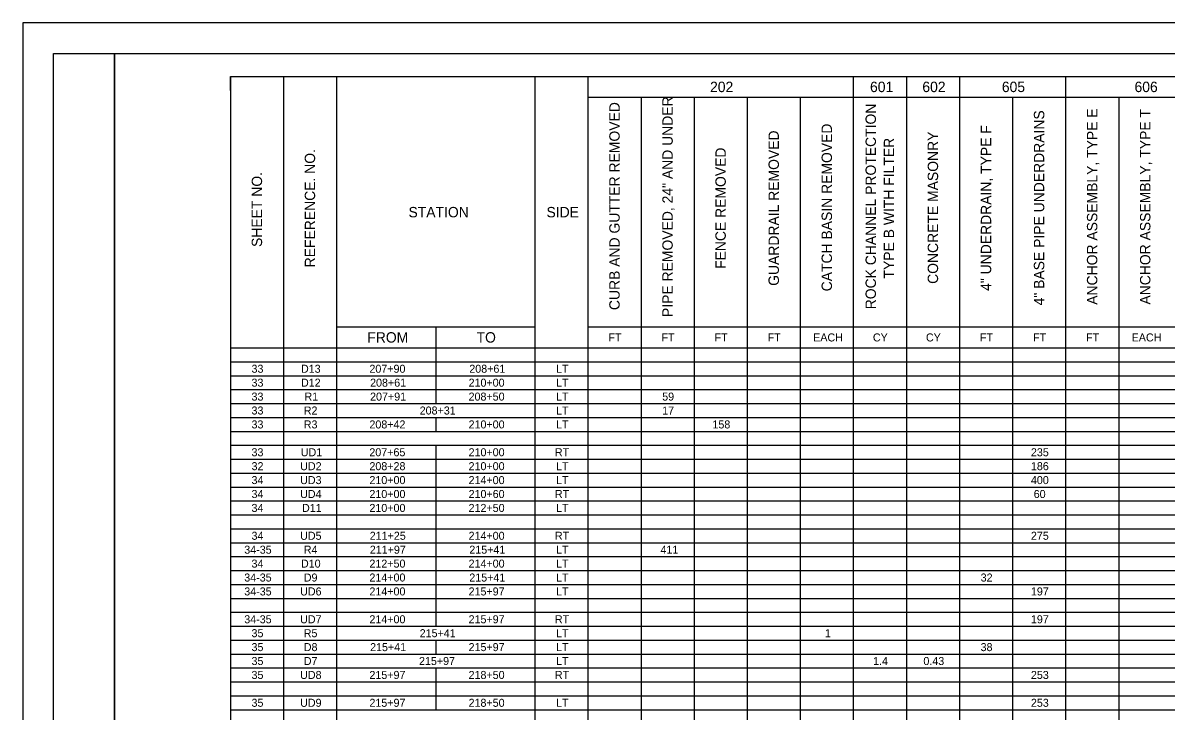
# Model space of a CAD drawing. Extents: x 0 to 37.4, y 0 to 22.
# Drawn here: x 0 to 18.72, y 10.72 to 22 of the extents above; entities that cross this region are included whole.
import ezdxf

# ---------------------------------------------------------------- set-up
doc = ezdxf.new("R2010")
doc.units = 0
for name, color, linetype in [('SH_Border', 7, 'Continuous'), ('SH_Cut_Line', 7, 'Continuous'), ('SH_Text', 7, 'Continuous')]:
    doc.layers.add(name, color=color, linetype=linetype)

msp = doc.modelspace()

# ---------------------------------------------------------------- linework, layer by layer
at = {"layer": 'SH_Border'}
for points in [[(0.5, 21.5), (1.5, 21.5), (1.5, 0.5), (0.5, 0.5)], [(1.5, 21.5), (33.5, 21.5), (33.5, 0.5), (1.5, 0.5)]]:
    msp.add_lwpolyline(points, close=True, dxfattribs=at)
at = {"layer": 'SH_Cut_Line'}
msp.add_lwpolyline([(0, 0), (34, 0), (34, 22), (0, 22)], close=True, dxfattribs=at)
at = {"layer": 'SH_Text'}
for p, q in [((3.398, 21.122), (30.117, 21.122)), ((3.398, 21.122), (3.398, 1.044)), ((4.268, 21.122), (4.268, 1.4)), ((5.137, 21.122), (5.137, 1.4)), ((8.386, 21.122), (8.386, 1.4)), ((9.255, 21.122), (9.255, 1.044)), ((13.601, 21.122), (13.601, 1.044)), ((14.471, 21.122), (14.471, 1.044)), ((15.34, 21.122), (15.34, 1.044)), ((17.078, 21.122), (17.078, 1.044)), ((9.255, 20.78), (30.117, 20.78)), ((10.124, 20.78), (10.124, 1.044)), ((10.994, 20.78), (10.994, 1.044)), ((11.863, 20.78), (11.863, 1.044)), ((12.732, 20.78), (12.732, 1.044)), ((16.209, 20.78), (16.209, 1.044)), ((17.948, 20.78), (17.948, 1.044)), ((5.137, 17.018), (8.386, 17.018)), ((6.761, 17.018), (6.761, 15.764)), ((9.255, 17.018), (30.117, 17.018)), ((3.398, 16.676), (30.117, 16.676)), ((3.398, 16.448), (30.117, 16.448)), ((3.398, 16.22), (30.117, 16.22)), ((3.398, 15.992), (30.117, 15.992)), ((3.398, 15.764), (30.117, 15.764)), ((3.398, 15.536), (30.117, 15.536)), ((6.761, 15.536), (6.761, 15.308)), ((3.398, 15.308), (30.117, 15.308)), ((3.398, 15.08), (30.117, 15.08)), ((6.761, 15.08), (6.761, 12.116)), ((3.398, 14.852), (30.117, 14.852)), ((3.398, 14.624), (30.117, 14.624)), ((3.398, 14.396), (30.117, 14.396)), ((3.398, 14.168), (30.117, 14.168)), ((3.398, 13.94), (30.117, 13.94)), ((3.398, 13.712), (30.117, 13.712)), ((3.398, 13.484), (30.117, 13.484)), ((3.398, 13.256), (30.117, 13.256)), ((3.398, 13.028), (30.117, 13.028)), ((3.398, 12.8), (30.117, 12.8)), ((3.398, 12.572), (30.117, 12.572)), ((3.398, 12.344), (30.117, 12.344)), ((3.398, 12.116), (30.117, 12.116)), ((3.398, 11.888), (30.117, 11.888)), ((6.761, 11.888), (6.761, 11.66)), ((3.398, 11.66), (30.117, 11.66)), ((3.398, 11.432), (30.117, 11.432)), ((6.761, 11.432), (6.761, 10.748)), ((3.398, 11.204), (30.117, 11.204)), ((3.398, 10.976), (30.117, 10.976)), ((3.398, 10.748), (30.117, 10.748))]:
    msp.add_line(p, q, dxfattribs=at)
for points in [[(3.398, 21.122), (3.398, 21.122), (3.398, 21.122), (3.398, 21.122)], [(3.398, 21.122), (3.398, 21.122), (3.398, 20.894), (3.398, 20.894)], [(3.398, 21.122), (3.398, 21.122), (3.398, 20.894), (3.398, 20.894)], [(3.398, 21.122), (3.398, 21.122), (3.398, 20.894), (3.398, 20.894)], [(3.398, 21.122), (3.398, 21.122), (3.398, 20.894), (3.398, 20.894)], [(3.398, 21.122), (3.398, 21.122), (3.398, 20.894), (3.398, 20.894)], [(3.398, 21.122), (3.398, 21.122), (3.398, 20.894), (3.398, 20.894)], [(3.398, 21.122), (3.398, 21.122), (3.398, 20.894), (3.398, 20.894)], [(3.398, 21.122), (3.398, 21.122), (3.398, 20.894), (3.398, 20.894)], [(3.398, 21.122), (3.398, 21.122), (3.398, 20.894), (3.398, 20.894)], [(3.398, 21.122), (3.398, 21.122), (3.398, 20.894), (3.398, 20.894)], [(3.398, 21.122), (3.398, 21.122), (3.398, 20.894), (3.398, 20.894)], [(3.398, 21.122), (3.398, 21.122), (3.398, 20.894), (3.398, 20.894)], [(3.398, 21.122), (3.398, 21.122), (3.398, 20.894), (3.398, 20.894)], [(3.398, 21.122), (3.398, 21.122), (3.398, 20.894), (3.398, 20.894)], [(3.398, 21.122), (3.398, 21.122), (3.398, 20.894), (3.398, 20.894)], [(3.398, 21.122), (3.398, 21.122), (3.398, 20.894), (3.398, 20.894)], [(3.398, 21.122), (3.398, 21.122), (3.398, 20.894), (3.398, 20.894)], [(3.398, 21.122), (3.398, 21.122), (3.398, 20.894), (3.398, 20.894)], [(3.398, 21.122), (3.398, 21.122), (3.398, 20.894), (3.398, 20.894)], [(3.398, 21.122), (3.398, 21.122), (3.398, 20.894), (3.398, 20.894)], [(3.398, 21.122), (3.398, 21.122), (3.398, 20.894), (3.398, 20.894)], [(3.398, 21.122), (3.398, 21.122), (3.398, 20.894), (3.398, 20.894)], [(3.398, 21.122), (3.398, 21.122), (3.398, 20.894), (3.398, 20.894)], [(3.398, 21.122), (3.398, 21.122), (3.398, 20.894), (3.398, 20.894)], [(3.398, 21.122), (3.398, 21.122), (3.398, 20.894), (3.398, 20.894)], [(3.398, 21.122), (3.398, 21.122), (3.398, 20.894), (3.398, 20.894)], [(3.398, 21.122), (3.398, 21.122), (3.398, 20.894), (3.398, 20.894)], [(3.398, 21.122), (3.398, 21.122), (3.398, 20.894), (3.398, 20.894)], [(3.398, 21.122), (3.398, 21.122), (3.398, 20.894), (3.398, 20.894)], [(3.398, 21.122), (3.398, 21.122), (3.398, 20.894), (3.398, 20.894)], [(3.398, 21.122), (3.398, 21.122), (3.398, 20.894), (3.398, 20.894)], [(3.398, 21.122), (3.398, 21.122), (3.398, 20.894), (3.398, 20.894)], [(3.398, 21.122), (3.398, 21.122), (3.398, 20.894), (3.398, 20.894)], [(3.398, 21.122), (3.398, 21.122), (3.398, 20.894), (3.398, 20.894)], [(3.398, 21.122), (3.398, 21.122), (3.398, 20.894), (3.398, 20.894)], [(3.398, 21.122), (3.398, 21.122), (3.398, 20.894), (3.398, 20.894)], [(3.398, 21.122), (3.398, 21.122), (3.398, 20.894), (3.398, 20.894)], [(3.398, 21.122), (3.398, 21.122), (3.398, 20.894), (3.398, 20.894)], [(3.398, 21.122), (3.398, 21.122), (3.398, 20.894), (3.398, 20.894)], [(3.398, 21.122), (3.398, 21.122), (3.398, 20.894), (3.398, 20.894)], [(3.398, 21.122), (3.398, 21.122), (3.398, 20.894), (3.398, 20.894)], [(3.398, 21.122), (3.398, 21.122), (3.398, 20.894), (3.398, 20.894)], [(3.398, 21.122), (3.398, 21.122), (3.398, 20.894), (3.398, 20.894)], [(3.398, 21.122), (3.398, 21.122), (3.398, 20.894), (3.398, 20.894)], [(3.398, 21.122), (3.398, 21.122), (3.398, 20.894), (3.398, 20.894)], [(3.398, 21.122), (3.398, 21.122), (3.398, 20.894), (3.398, 20.894)], [(3.398, 21.122), (3.398, 21.122), (3.398, 20.894), (3.398, 20.894)], [(3.398, 21.122), (3.398, 21.122), (3.398, 20.894), (3.398, 20.894)], [(3.398, 21.122), (3.398, 21.122), (3.398, 20.894), (3.398, 20.894)], [(3.398, 21.122), (3.398, 21.122), (3.398, 20.894), (3.398, 20.894)], [(3.398, 21.122), (3.398, 21.122), (3.398, 20.894), (3.398, 20.894)], [(3.398, 21.122), (3.398, 21.122), (3.398, 20.894), (3.398, 20.894)], [(3.398, 21.122), (3.398, 21.122), (3.398, 20.894), (3.398, 20.894)], [(3.398, 21.122), (3.398, 21.122), (3.398, 20.894), (3.398, 20.894)], [(3.398, 21.122), (3.398, 21.122), (3.398, 20.894), (3.398, 20.894)], [(3.398, 21.122), (3.398, 21.122), (3.398, 20.894), (3.398, 20.894)], [(3.398, 21.122), (3.398, 21.122), (3.398, 20.894), (3.398, 20.894)], [(3.398, 21.122), (3.398, 21.122), (3.398, 20.894), (3.398, 20.894)], [(3.398, 21.122), (3.398, 21.122), (3.398, 20.894), (3.398, 20.894)], [(3.398, 21.122), (3.398, 21.122), (3.398, 20.894), (3.398, 20.894)], [(3.398, 21.122), (3.398, 21.122), (3.398, 20.894), (3.398, 20.894)], [(3.398, 21.122), (3.398, 21.122), (3.398, 20.894), (3.398, 20.894)], [(3.398, 21.122), (3.398, 21.122), (3.398, 20.894), (3.398, 20.894)], [(3.398, 21.122), (3.398, 21.122), (3.398, 20.894), (3.398, 20.894)], [(3.398, 21.122), (3.398, 21.122), (3.398, 20.894), (3.398, 20.894)], [(3.398, 21.122), (3.398, 21.122), (3.398, 20.894), (3.398, 20.894)], [(3.398, 21.122), (3.398, 21.122), (3.398, 20.894), (3.398, 20.894)]]:
    msp.add_lwpolyline(points, close=True, dxfattribs=at)

# ---------------------------------------------------------------- texts
for s, height, p in [('202', 0.1704, (11.255, 20.866)), ('601', 0.1704, (13.875, 20.866)), ('602', 0.1704, (14.732, 20.866)), ('605', 0.1704, (16.034, 20.866)), ('606', 0.1704, (18.207, 20.866)), ('STATION', 0.1704, (6.316, 18.814)), ('SIDE', 0.1704, (8.576, 18.814)), ('FROM', 0.1704, (5.641, 16.762)), ('TO', 0.1704, (7.431, 16.762)), ('FT', 0.1311, (9.591, 16.781)), ('FT', 0.1311, (10.46, 16.781)), ('FT', 0.1311, (11.329, 16.781)), ('FT', 0.1311, (12.198, 16.781)), ('EACH', 0.1311, (12.944, 16.781)), ('CY', 0.1311, (13.922, 16.781)), ('CY', 0.1311, (14.791, 16.781)), ('FT', 0.1311, (15.675, 16.781)), ('FT', 0.1311, (16.545, 16.781)), ('FT', 0.1311, (17.414, 16.781)), ('EACH', 0.1311, (18.16, 16.781)), ('33', 0.1311, (3.745, 16.268)), ('D13', 0.1311, (4.555, 16.268)), ('207+90', 0.1311, (5.676, 16.268)), ('208+61', 0.1311, (7.312, 16.268)), ('LT', 0.1311, (8.732, 16.268)), ('33', 0.1311, (3.745, 16.04)), ('D12', 0.1311, (4.555, 16.04)), ('208+61', 0.1311, (5.687, 16.04)), ('210+00', 0.1311, (7.3, 16.04)), ('LT', 0.1311, (8.732, 16.04)), ('33', 0.1311, (3.745, 15.812)), ('R1', 0.1311, (4.612, 15.812)), ('207+91', 0.1311, (5.687, 15.812)), ('208+50', 0.1311, (7.3, 15.812)), ('LT', 0.1311, (8.732, 15.812)), ('59', 0.1311, (10.471, 15.812)), ('33', 0.1311, (3.745, 15.584)), ('R2', 0.1311, (4.601, 15.584)), ('208+31', 0.1311, (6.499, 15.584)), ('LT', 0.1311, (8.732, 15.584)), ('17', 0.1311, (10.471, 15.584)), ('33', 0.1311, (3.745, 15.356)), ('R3', 0.1311, (4.601, 15.356)), ('208+42', 0.1311, (5.676, 15.356)), ('210+00', 0.1311, (7.3, 15.356)), ('LT', 0.1311, (8.732, 15.356)), ('158', 0.1311, (11.294, 15.356)), ('33', 0.1311, (3.745, 14.9)), ('UD1', 0.1311, (4.552, 14.9)), ('207+65', 0.1311, (5.675, 14.9)), ('210+00', 0.1311, (7.3, 14.9)), ('RT', 0.1311, (8.714, 14.9)), ('235', 0.1311, (16.51, 14.9)), ('32', 0.1311, (3.746, 14.672)), ('UD2', 0.1311, (4.542, 14.672)), ('208+28', 0.1311, (5.676, 14.672)), ('210+00', 0.1311, (7.3, 14.672)), ('LT', 0.1311, (8.732, 14.672)), ('186', 0.1311, (16.51, 14.672)), ('34', 0.1311, (3.745, 14.444)), ('UD3', 0.1311, (4.541, 14.444)), ('210+00', 0.1311, (5.676, 14.444)), ('214+00', 0.1311, (7.3, 14.444)), ('LT', 0.1311, (8.732, 14.444)), ('400', 0.1311, (16.51, 14.444)), ('34', 0.1311, (3.745, 14.216)), ('UD4', 0.1311, (4.541, 14.216)), ('210+00', 0.1311, (5.676, 14.216)), ('210+60', 0.1311, (7.3, 14.216)), ('RT', 0.1311, (8.714, 14.216)), ('60', 0.1311, (16.556, 14.216)), ('34', 0.1311, (3.745, 13.988)), ('D11', 0.1311, (4.572, 13.988)), ('210+00', 0.1311, (5.676, 13.988)), ('212+50', 0.1311, (7.3, 13.988)), ('LT', 0.1311, (8.732, 13.988)), ('34', 0.1311, (3.745, 13.532)), ('UD5', 0.1311, (4.541, 13.532)), ('211+25', 0.1311, (5.681, 13.532)), ('214+00', 0.1311, (7.3, 13.532)), ('RT', 0.1311, (8.714, 13.532)), ('275', 0.1311, (16.51, 13.532)), ('34-35', 0.1311, (3.626, 13.304)), ('R4', 0.1311, (4.601, 13.304)), ('211+97', 0.1311, (5.682, 13.304)), ('215+41', 0.1311, (7.312, 13.304)), ('LT', 0.1311, (8.732, 13.304)), ('411', 0.1311, (10.443, 13.304)), ('34', 0.1311, (3.745, 13.076)), ('D10', 0.1311, (4.555, 13.076)), ('212+50', 0.1311, (5.676, 13.076)), ('214+00', 0.1311, (7.3, 13.076)), ('LT', 0.1311, (8.732, 13.076)), ('34-35', 0.1311, (3.626, 12.848)), ('D9', 0.1311, (4.601, 12.848)), ('214+00', 0.1311, (5.676, 12.848)), ('215+41', 0.1311, (7.312, 12.848)), ('LT', 0.1311, (8.732, 12.848)), ('32', 0.1311, (15.687, 12.848)), ('34-35', 0.1311, (3.626, 12.62)), ('UD6', 0.1311, (4.541, 12.62)), ('214+00', 0.1311, (5.676, 12.62)), ('215+97', 0.1311, (7.3, 12.62)), ('LT', 0.1311, (8.732, 12.62)), ('197', 0.1311, (16.51, 12.62)), ('34-35', 0.1311, (3.626, 12.164)), ('UD7', 0.1311, (4.541, 12.164)), ('214+00', 0.1311, (5.676, 12.164)), ('215+97', 0.1311, (7.3, 12.164)), ('RT', 0.1311, (8.714, 12.164)), ('197', 0.1311, (16.51, 12.164)), ('35', 0.1311, (3.745, 11.936)), ('R5', 0.1311, (4.6, 11.936)), ('215+41', 0.1311, (6.499, 11.936)), ('LT', 0.1311, (8.732, 11.936)), ('1', 0.131, (13.136, 11.936)), ('35', 0.1311, (3.745, 11.708)), ('D8', 0.1311, (4.601, 11.708)), ('215+41', 0.1311, (5.687, 11.708)), ('215+97', 0.1311, (7.3, 11.708)), ('LT', 0.1311, (8.732, 11.708)), ('38', 0.1311, (15.686, 11.708)), ('35', 0.1311, (3.745, 11.48)), ('D7', 0.1311, (4.601, 11.48)), ('215+97', 0.1311, (6.488, 11.48)), ('LT', 0.1311, (8.732, 11.48)), ('1.4', 0.1311, (13.925, 11.48)), ('0.43', 0.1311, (14.749, 11.48)), ('35', 0.1311, (3.745, 11.252)), ('UD8', 0.1311, (4.541, 11.252)), ('215+97', 0.1311, (5.676, 11.252)), ('218+50', 0.1311, (7.3, 11.252)), ('RT', 0.1311, (8.714, 11.252)), ('253', 0.1311, (16.51, 11.252)), ('35', 0.1311, (3.745, 10.796)), ('UD9', 0.1311, (4.541, 10.796)), ('215+97', 0.1311, (5.676, 10.796)), ('218+50', 0.1311, (7.3, 10.796)), ('LT', 0.1311, (8.732, 10.796)), ('253', 0.1311, (16.51, 10.796))]:
    msp.add_text(s, height=height, dxfattribs=at).set_placement(p)
for s, height, p in [('PIPE REMOVED, 24" AND UNDER', 0.17043, (10.644, 17.181)), ('CURB AND GUTTER REMOVED', 0.17043, (9.775, 17.295)), ('ROCK CHANNEL PROTECTION ', 0.17043, (13.972, 17.308)), ('4" BASE PIPE UNDERDRAINS', 0.17043, (16.729, 17.371)), ('ANCHOR ASSEMBLY, TYPE E', 0.17043, (17.598, 17.382)), ('ANCHOR ASSEMBLY, TYPE T', 0.17043, (18.467, 17.385)), ('GUARDRAIL REMOVED', 0.17043, (12.383, 17.692)), ('CATCH BASIN REMOVED', 0.17043, (13.252, 17.602)), ('4" UNDERDRAIN, TYPE F', 0.17043, (15.86, 17.609)), ('TYPE B WITH FILTER', 0.17043, (14.27, 17.812)), ('CONCRETE MASONRY', 0.17043, (14.99, 17.724)), ('REFERENCE. NO.', 0.17043, (4.787, 17.995)), ('FENCE REMOVED', 0.17043, (11.513, 17.969)), ('SHEET NO.', 0.1704, (3.918, 18.329))]:
    msp.add_text(s, height=height, rotation=90, dxfattribs=at).set_placement(p)

doc.saveas('drawing.dxf')
